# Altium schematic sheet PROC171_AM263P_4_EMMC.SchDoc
size 431 x 279 mm; DocumentNumber: 9; SheetNumber: 9; SheetTotal: 27
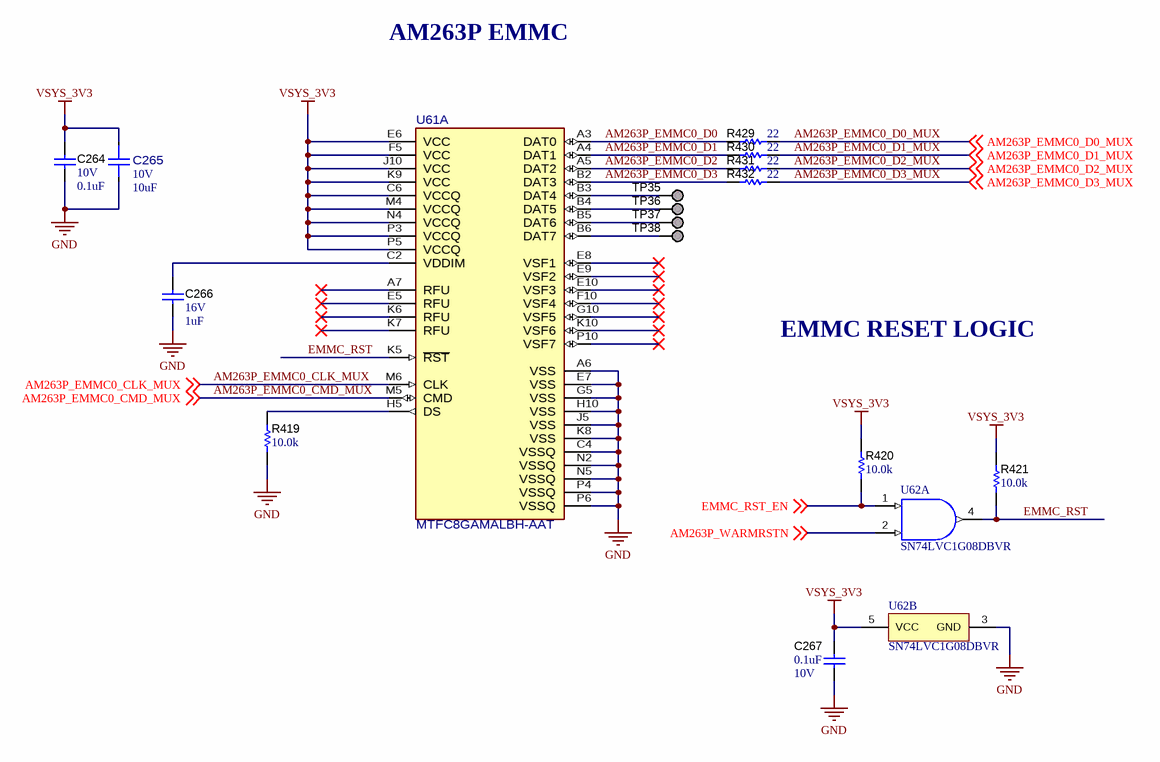
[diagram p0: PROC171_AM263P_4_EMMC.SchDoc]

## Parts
C264  VDC_V: 10V  ValueDisplayed: 0.1uF  [0402]  (hidden comment: 885012105010)
C265  ValueDisplayed: 10uF  VDC_V: 10V  [FP-KGM05CR51A106MH_0402-MFG]  (hidden comment: KGM05CR51A106MH)
C266  VDC_V: 16V  ValueDisplayed: 1uF  [0402]  (hidden comment: C1005X6S1C105K050BC)
C267  VDC_V: 10V  ValueDisplayed: 0.1uF  [0402]  (hidden comment: 885012105010)
R419  ValueDisplayed: 10.0k  [0402]  (hidden comment: ERJ-2RKF1002X)
R420  ValueDisplayed: 10.0k  [0402]  (hidden comment: ERJ-2RKF1002X)
R421  ValueDisplayed: 10.0k  [0402L]  (hidden comment: CRCW040210K0FKED)
R429  Res_ohm: 22  [FP-CRCW020122R0FNED_0201 (0603 metric)-MFG]  (hidden comment: CRCW020122R0FNED)
R430  Res_ohm: 22  [FP-CRCW020122R0FNED_0201 (0603 metric)-MFG]  (hidden comment: CRCW020122R0FNED)
R431  Res_ohm: 22  [FP-CRCW020122R0FNED_0201 (0603 metric)-MFG]  (hidden comment: CRCW020122R0FNED)
R432  Res_ohm: 22  [FP-CRCW020122R0FNED_0201 (0603 metric)-MFG]  (hidden comment: CRCW020122R0FNED)
TP35  TESTPOINT  [TP_25MIL-SMT]  (value not drawn)  (no BOM)
TP36  TESTPOINT  [TP_25MIL-SMT]  (value not drawn)  (no BOM)
TP37  TESTPOINT  [TP_25MIL-SMT]  (value not drawn)  (no BOM)
TP38  TESTPOINT  [TP_25MIL-SMT]  (value not drawn)  (no BOM)
U61  MTFC8GAMALBH-AAT  [FP-MTFC8GAMALBH-AAT_TFBGA153-MFG]  (part A of 3)
U62  SN74LVC1G08DBVR  [DBV0005A_N]  (parts A,B of 2)

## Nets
GND: C264.2 C265.2 C266.2 C267.2 R419.2 U61.A6(VSS) U61.C4(VSSQ) U61.E7(VSS) U61.G5(VSS) U61.H10(VSS) U61.J5(VSS) U61.K8(VSS) U61.N2(VSSQ) U61.N5(VSSQ) U61.P4(VSSQ) U61.P6(VSSQ) U62.3(GND)
VSYS_3V3: C264.1 C265.1 C267.1 R420.1 R421.2 U61.C6(VCCQ) U61.E6(VCC) U61.F5(VCC) U61.J10(VCC) U61.K9(VCC) U61.M4(VCCQ) U61.N4(VCCQ) U61.P3(VCCQ) U61.P5(VCCQ) U62.5(VCC)
AM263P_EMMC0_CLK_MUX: U61.M6(CLK) ; off-sheet AM263P_EMMC0_CLK_MUX
AM263P_EMMC0_CMD_MUX: U61.M5(CMD) ; off-sheet AM263P_EMMC0_CMD_MUX
AM263P_EMMC0_D0: R429.1 U61.A3(DAT0)
AM263P_EMMC0_D0_MUX: R429.2 ; off-sheet AM263P_EMMC0_D0_MUX
AM263P_EMMC0_D1: R430.1 U61.A4(DAT1)
AM263P_EMMC0_D1_MUX: R430.2 ; off-sheet AM263P_EMMC0_D1_MUX
AM263P_EMMC0_D2: R431.1 U61.A5(DAT2)
AM263P_EMMC0_D2_MUX: R431.2 ; off-sheet AM263P_EMMC0_D2_MUX
AM263P_EMMC0_D3: R432.1 U61.B2(DAT3)
AM263P_EMMC0_D3_MUX: R432.2 ; off-sheet AM263P_EMMC0_D3_MUX
AM263P_WARMRSTN: U62.2(B) ; off-sheet AM263P_WARMRSTN
EMMC_RST: R421.1 U61.K5(~{RST}) U62.4(Y)
EMMC_RST_EN: R420.2 U62.1(A) ; off-sheet EMMC_RST_EN
NetC266_1: C266.1 U61.C2(VDDIM)
NetR419_1: R419.1 U61.H5(DS)
NetTP35_1: TP35.1 U61.B3(DAT4)
NetTP36_1: TP36.1 U61.B4(DAT5)
NetTP37_1: TP37.1 U61.B5(DAT6)
NetTP38_1: TP38.1 U61.B6(DAT7)

Not connected (* = marked no-connect by the designer): U61 A7(RFU)* E5(RFU)* E8(VSF1)* E9(VSF2)* E10(VSF3)* F10(VSF4)* G10(VSF5)* K6(RFU)* K7(RFU)* K10(VSF6)* P10(VSF7)*

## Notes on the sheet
- AM263P EMMC
- EMMC RESET LOGIC

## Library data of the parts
C264 C267 = CMP-0006221-2: CAP, CERM, 0.1 uF, 10 V, +/- 20%, X5R, 0402; Manufacturer: Wurth Elektronik; TaMin_C: -55°C; Polarized: N; SizeAreaWB_mm2: 3; Value1: Unknown; U/M: EA; Value: 0.1uF; TaMax_C: 85°C; SizeZ_mm: 0.6; SizeX_mm: 1; SizeY_mm: 0.5; Cap_F: 100nF; AEC Category: Q200
C265 = CMP-0043010-1: 10 µF ±20% 10V Ceramic Capacitor X5R 0402 (1005 Metric); Manufacturer: KYOCERA AVX; AEC Qualified: No; Cap_F: 10µF; SizeZ_mm: 0.7mm; TempCo: 15%; Value: 10µF
C266 = CMP-0006286-2: CAP, CERM, 1 uF, 16 V, +/- 10%, X6S, 0402; Manufacturer: TDK; TaMin_C: -55°C; ESR_ohm: 0.011416; Polarized: N; SizeAreaWB_mm2: 3; Value1: 0.011416 ohm; U/M: EA; Value: 1uF; TaMax_C: 105°C; SizeZ_mm: 0.6; SizeX_mm: 1; SizeY_mm: 0.5; Cap_F: 1µF; IRMS_A: 1.483A; AEC Category: Q200
R419 R420 = CMP-0026658-1: RES, 10.0 k, 1%, 0.1 W, 0402; Manufacturer: Panasonic; Power_W: 100mW; TempCo: 100 ppm/C; Value_Code: 10k0; U/M: EA; Value: 10.0k; EIA_Code: E96; Res_ohm: 10k; SizeX_mm: 1; SizeY_mm: 0.5; SizeZ_mm: 0.6; Value2: 0.1W; VDC_V: 50V; AEC Category: Q200
R421 = CMP-0025958-3: RES, 10.0 k, 1%, 0.063 W, AEC-Q200 Grade 0, 0402; Manufacturer: Vishay-Dale; Power_W: 63mW; TempCo: 100 ppm/C; Value_Code: 10k0; Value: 10.0k; EIA_Code: E96; Res_ohm: 10k; SizeX_mm: 1; SizeY_mm: 0.5; SizeZ_mm: 0.6; Value2: 0.063W; AEC Qualified: Y; VDC_V: 50V; AEC Category: Q200; AEC Grade: 0
R429-R432 = CMP-0087090-2: RES Thick Film SMD 22Ω 1% 1/20W 0201 200ppm/°C; Manufacturer: Vishay; SizeZ_mm: 0.28mm; VDC_V: 30V; Power_W: 50mW; AEC Qualified: No
TP35-TP38 = CMP-0078143-3: TEST POINT.  No entry in BOM.
U61 = CMP-0091989-1: FLASH - NAND Memory IC 64Gb (8G x 8) MMC 153-TFBGA (11.5x13); Manufacturer: Micron Technology; Standoff Height: 0.174mm; Memory Size: 8GBytes; Memory Type: FLASH,NAND; TaMax_C: +105°C; Min Supply Voltage: 2.7V; TaMin_C: -40°C; Max Supply Voltage: 3.6V; Interface: Other; SizeZ_mm: 1.1mm; AEC Qualified: No
U62 = CMP-0051588-2: Single 2-Input Positive-AND Gate, DBV0005A, LARGE T&R; Manufacturer: Texas Instruments; Logic: True; ICC @ Nom Voltage(Max)(mA): 0.01; VCC(Min)(V): 1.65; Bits(#): 1; Rating: Catalog; Schmitt Trigger: No; Voltage(Nom)(V): 1.8,2.5,3.3,5; Output Drive (IOL/IOH)(Max)(mA): 32/-32; Gate Type: AND; tpd @ Nom Voltage(Max)(ns): 4.5,6,4,5; VCC(Max)(V): 5.5; Output Type: CMOS; F @ Nom Voltage(Max)(Mhz): 150; Input Type: CMOS/TTL; Technology Family: LVC; AEC Category: Q200; AEC Qualified: N; CompType: IC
